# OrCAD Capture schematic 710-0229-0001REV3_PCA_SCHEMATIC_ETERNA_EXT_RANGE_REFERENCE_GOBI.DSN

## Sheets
1 01) Title: title: PCA SCH, ETERNA EXT RANGE REFERENCE, GOBI; rev: 03; note: 710-0229-0001
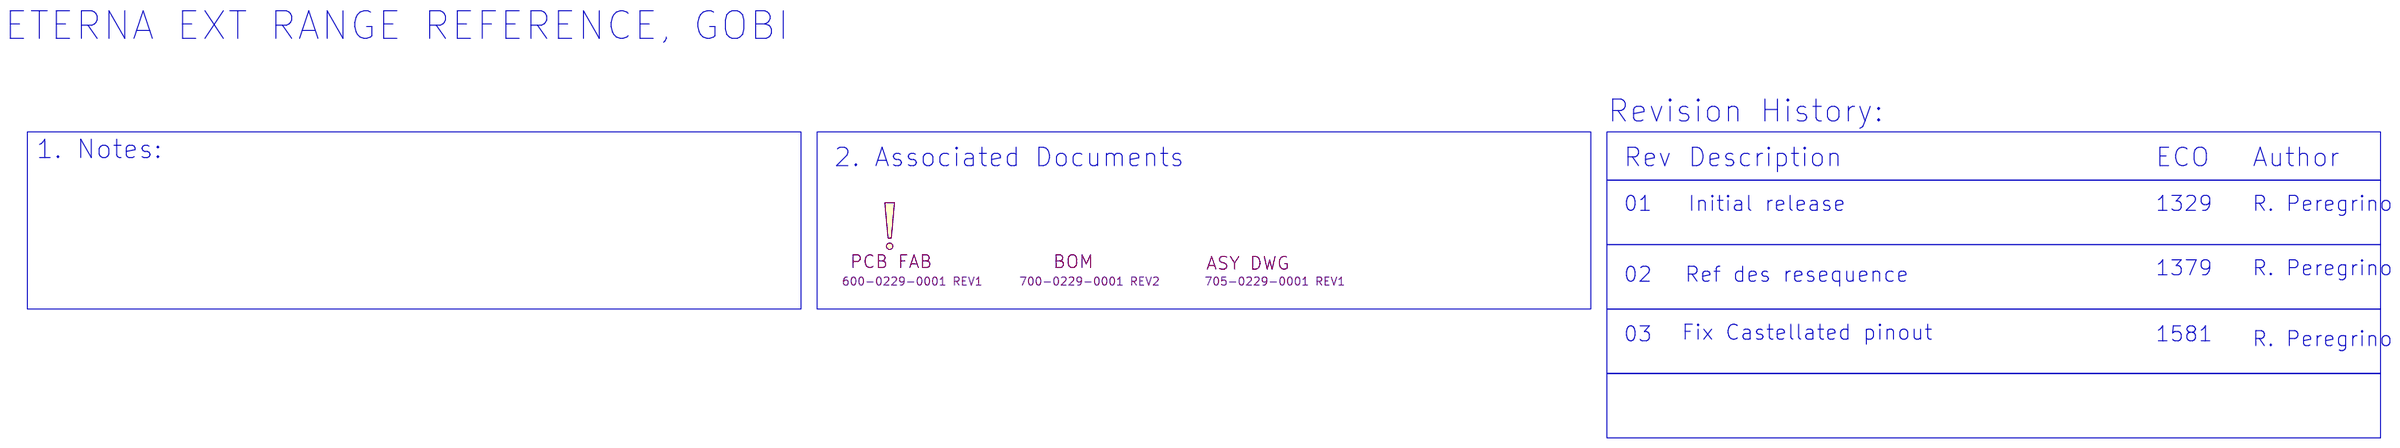
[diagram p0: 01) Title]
2 02) ETERNA: size B
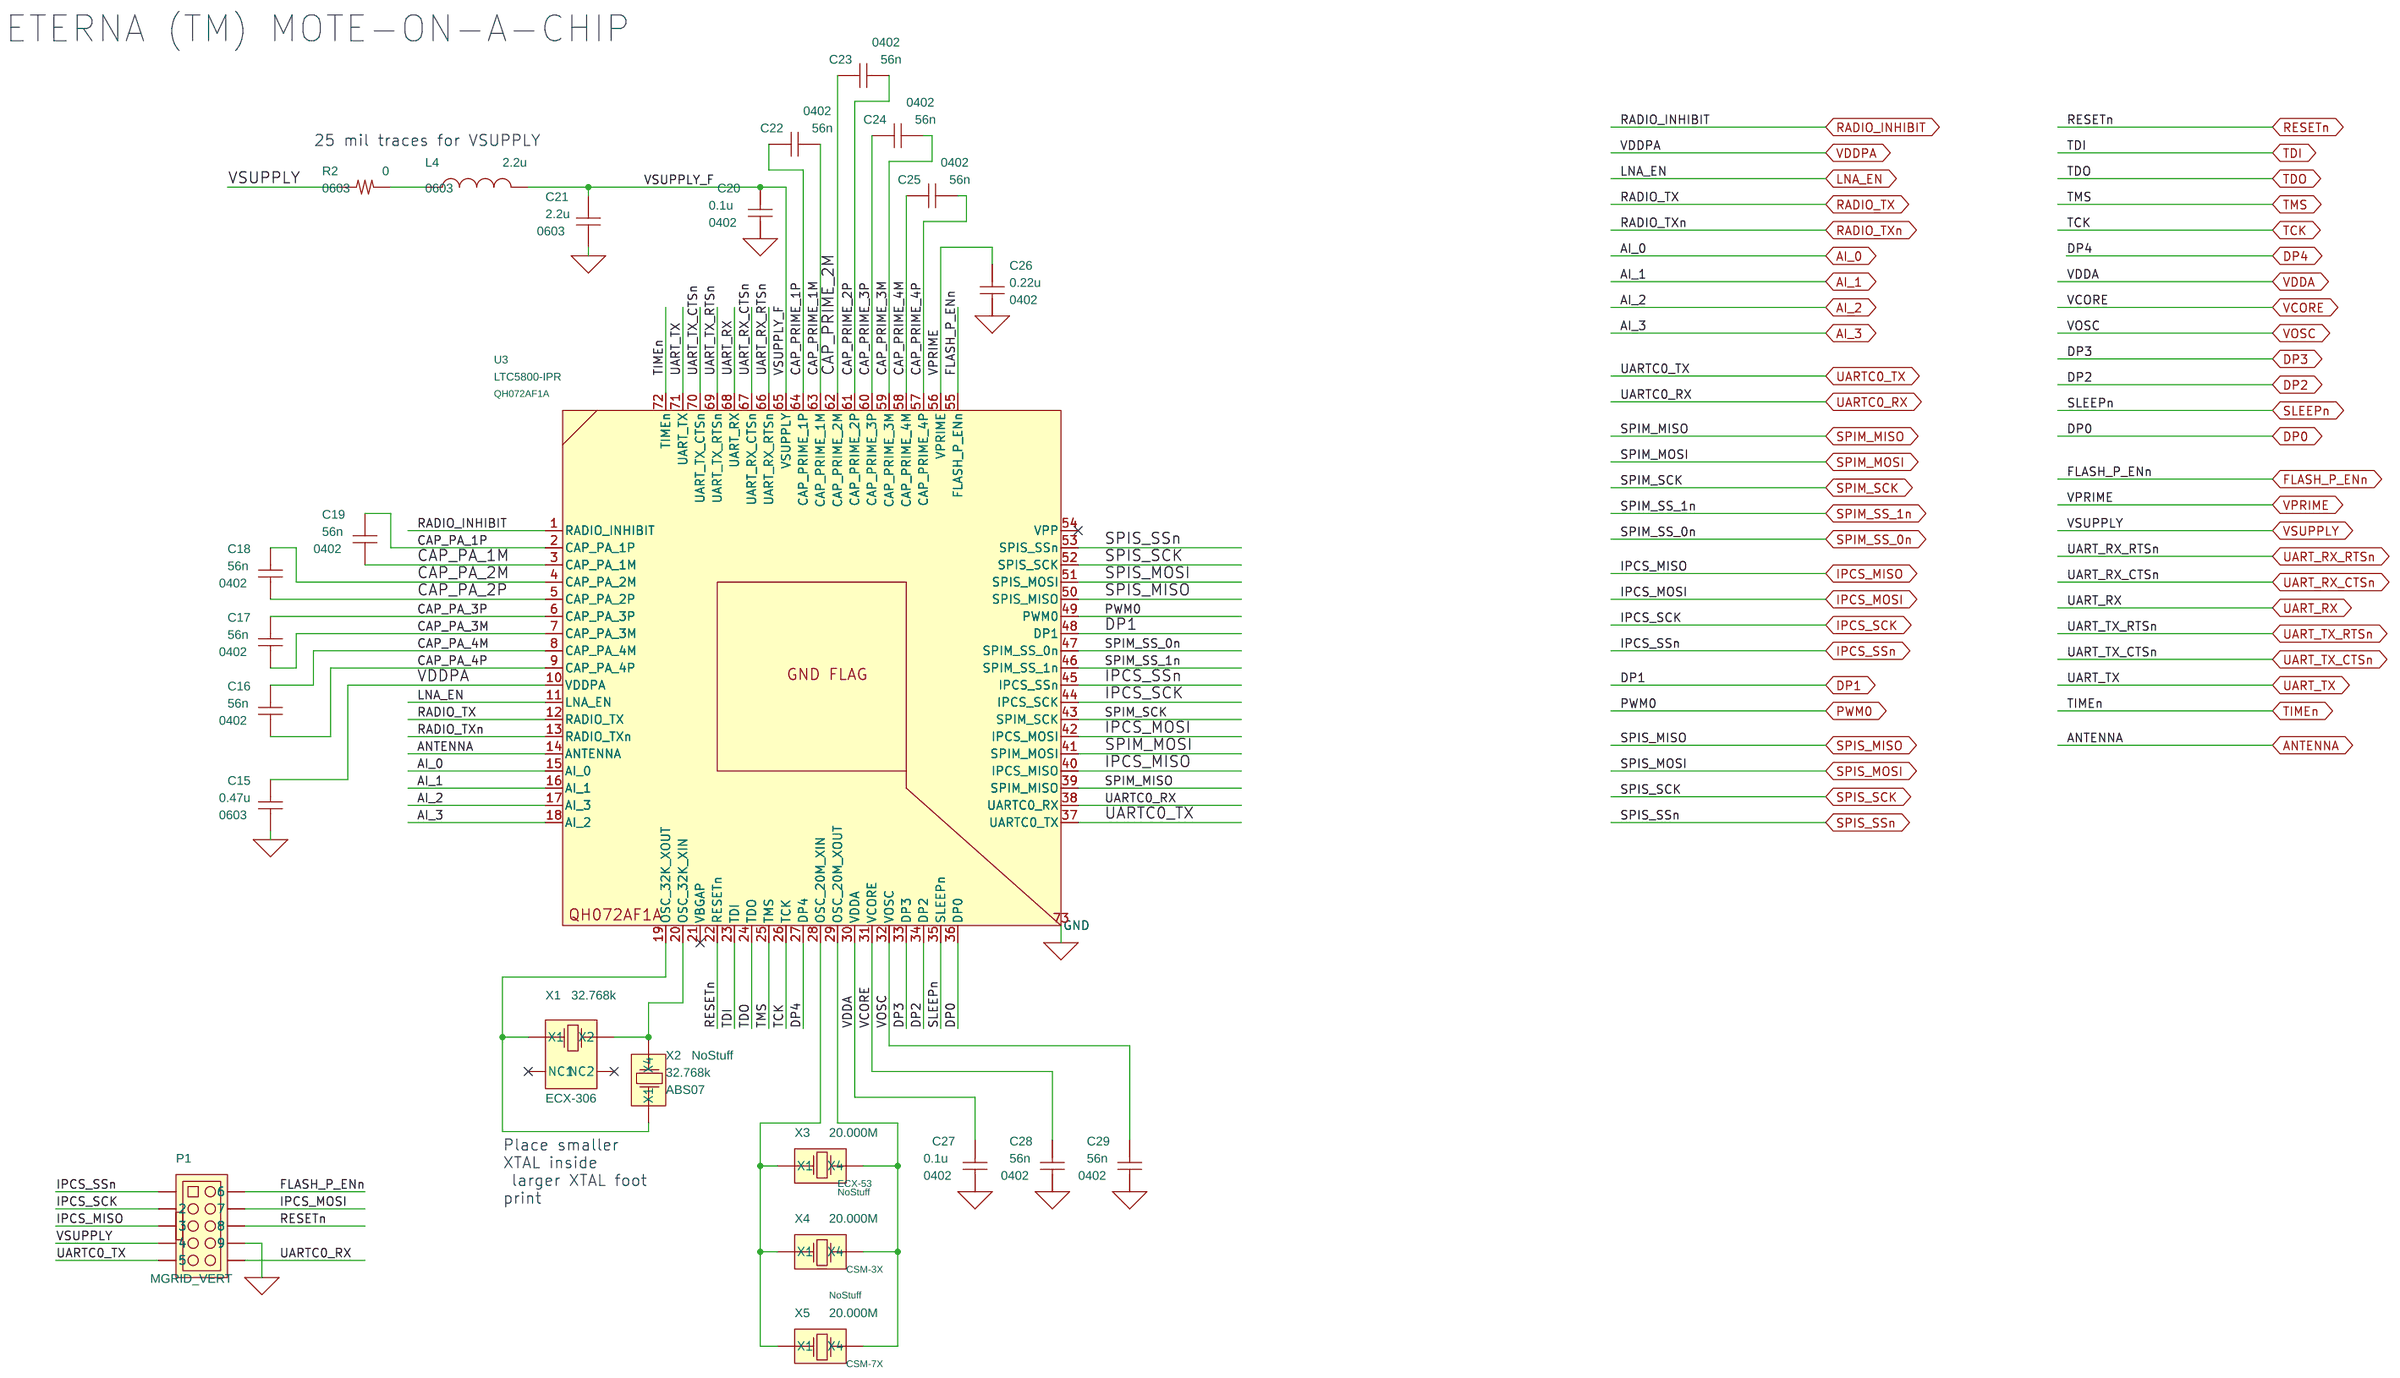
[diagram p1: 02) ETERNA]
3 03) CASTLE: size Custom
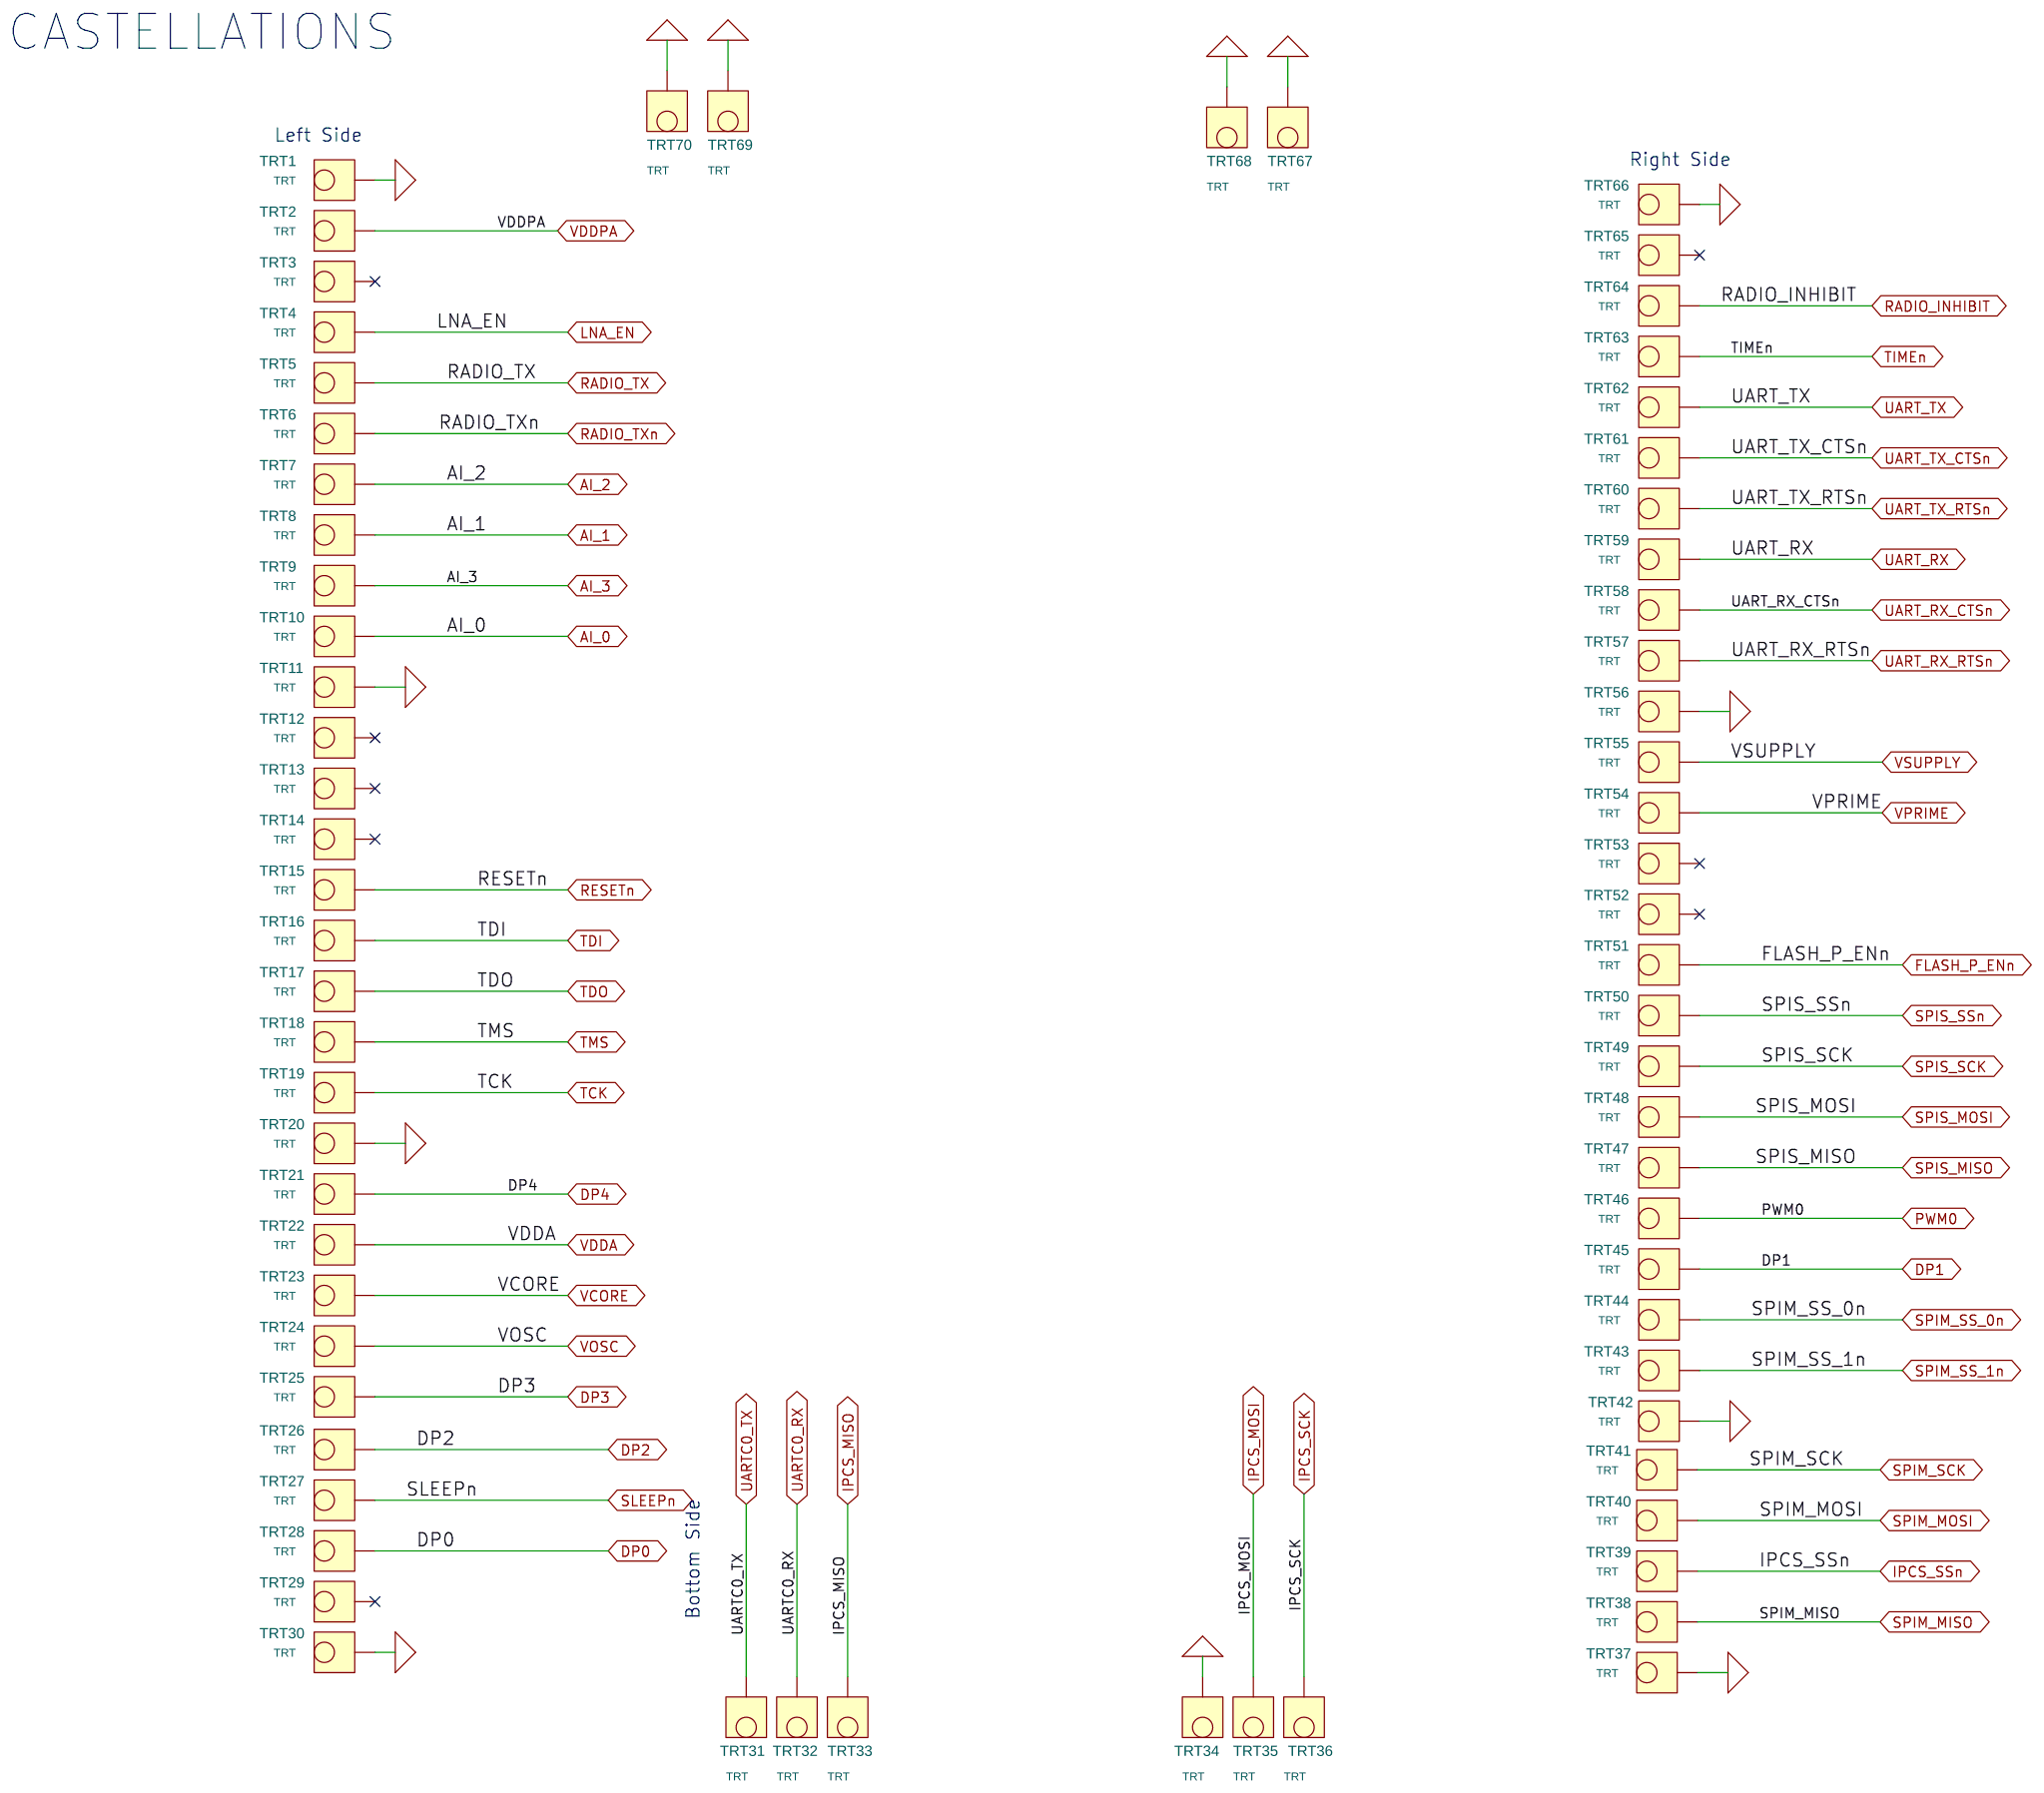
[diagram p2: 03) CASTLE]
4 04) PA, LNA: size B
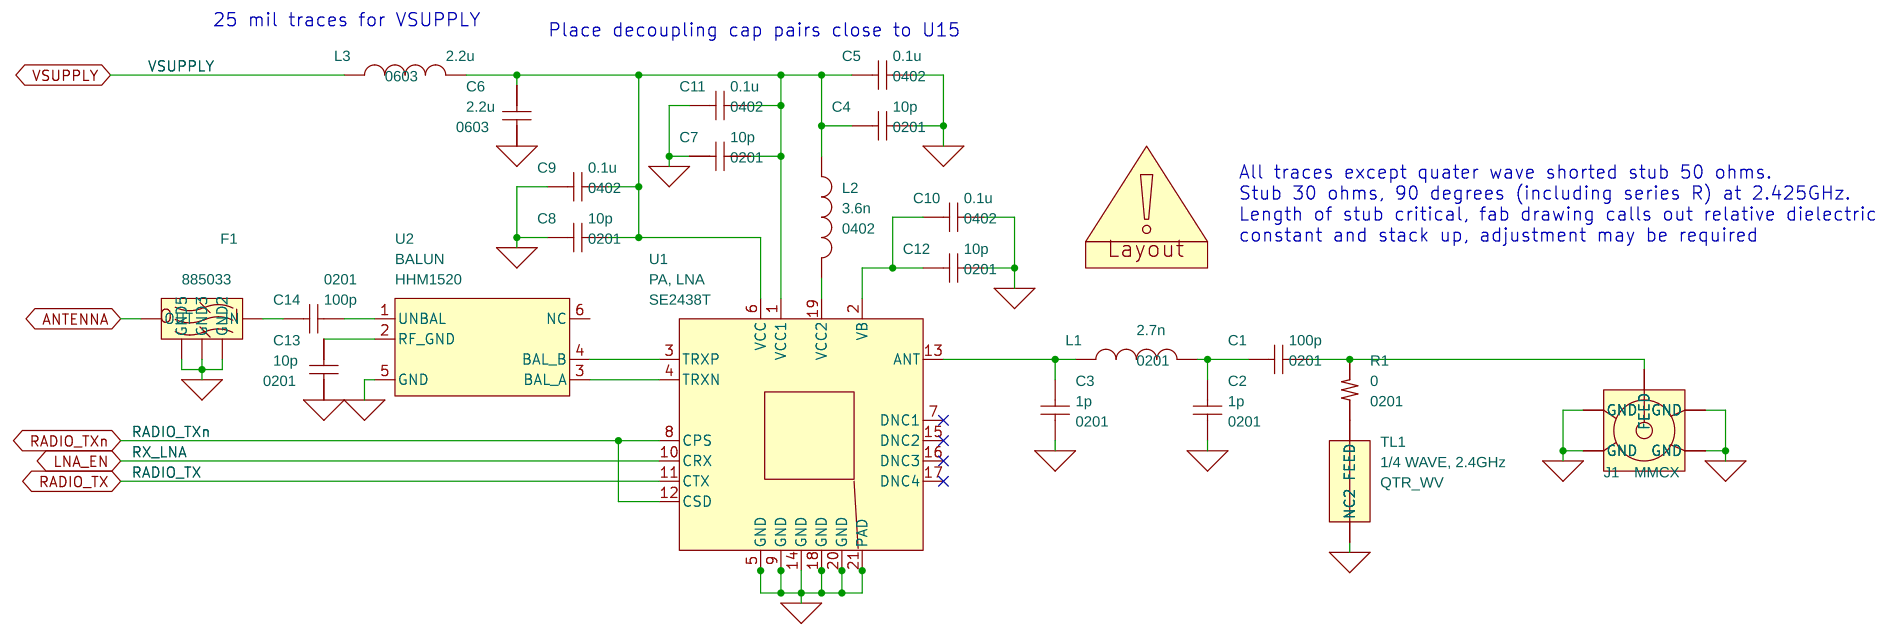
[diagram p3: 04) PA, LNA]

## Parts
sheet 01) Title
WARNINGL1  CALLOUT_PCB_FAB
WARNINGL2  CALLOUT_BOM
WARNINGL3  CALLOUT_ASSY_DWG
sheet 02) ETERNA
C15  0.47u  [0603]
C16  56n  [0402]
C17  56n  [0402]
C18  56n  [0402]
C19  56n  [0402]
C20  0.1u  [0402]
C21  2.2u  [0603]
C22  56n  [0402]
C23  56n  [0402]
C24  56n  [0402]
C25  56n  [0402]
C26  0.22u  [0402]
C27  0.1u  [0402]
C28  56n  [0402]
C29  56n  [0402]
L4  2.2u  [0603]
P1  MGRID_VERT  [HDR_2X5_2MM_SHRD]
R2  0  [0603]
U3  LTC5800-IPR  [QH072AF1A]
X1  32.768k  [ECX-306]
X2  32.768k  [ABS07]
X3  20.000M  [ECX-53]
X4  20.000M  [CSM-3X]
X5  20.000M  [CSM-7X]
sheet 03) CASTLE
TRT1  TP35_0  [TRT]
TRT2  TP35_0  [TRT]
TRT3  TP35_0  [TRT]
TRT4  TP35_0  [TRT]
TRT5  TP35_0  [TRT]
TRT6  TP35_0  [TRT]
TRT7  TP35_0  [TRT]
TRT8  TP35_0  [TRT]
TRT9  TP35_0  [TRT]
TRT10  TP35_0  [TRT]
TRT11  TP35_0  [TRT]
TRT12  TP35_0  [TRT]
TRT13  TP35_0  [TRT]
TRT14  TP35_0  [TRT]
TRT15  TP35_0  [TRT]
TRT16  TP35_0  [TRT]
TRT17  TP35_0  [TRT]
TRT18  TP35_0  [TRT]
TRT19  TP35_0  [TRT]
TRT20  TP35_0  [TRT]
TRT21  TP35_0  [TRT]
TRT22  TP35_0  [TRT]
TRT23  TP35_0  [TRT]
TRT24  TP35_0  [TRT]
TRT25  TP35_0  [TRT]
TRT26  TP35_0  [TRT]
TRT27  TP35_0  [TRT]
TRT28  TP35_0  [TRT]
TRT29  TP35_0  [TRT]
TRT30  TP35_0  [TRT]
TRT31  TP35_0  [TRT]
TRT32  TP35_0  [TRT]
TRT33  TP35_0  [TRT]
TRT34  TP35_0  [TRT]
TRT35  TP35_0  [TRT]
TRT36  TP35_0  [TRT]
TRT37  TP35_0  [TRT]
TRT38  TP35_0  [TRT]
TRT39  TP35_0  [TRT]
TRT40  TP35_0  [TRT]
TRT41  TP35_0  [TRT]
TRT42  TP35_0  [TRT]
TRT43  TP35_0  [TRT]
TRT44  TP35_0  [TRT]
TRT45  TP35_0  [TRT]
TRT46  TP35_0  [TRT]
TRT47  TP35_0  [TRT]
TRT48  TP35_0  [TRT]
TRT49  TP35_0  [TRT]
TRT50  TP35_0  [TRT]
TRT51  TP35_0  [TRT]
TRT52  TP35_0  [TRT]
TRT53  TP35_0  [TRT]
TRT54  TP35_0  [TRT]
TRT55  TP35_0  [TRT]
TRT56  TP35_0  [TRT]
TRT57  TP35_0  [TRT]
TRT58  TP35_0  [TRT]
TRT59  TP35_0  [TRT]
TRT60  TP35_0  [TRT]
TRT61  TP35_0  [TRT]
TRT62  TP35_0  [TRT]
TRT63  TP35_0  [TRT]
TRT64  TP35_0  [TRT]
TRT65  TP35_0  [TRT]
TRT66  TP35_0  [TRT]
TRT67  TP35_0  [TRT]
TRT68  TP35_0  [TRT]
TRT69  TP35_0  [TRT]
TRT70  TP35_0  [TRT]
sheet 04) PA, LNA
C1  100p  [0201]
C2  1p  [0201]
C3  1p  [0201]
C4  10p  [0201]
C5  0.1u  [0402]
C6  2.2u  [0603]
C7  10p  [0201]
C8  10p  [0201]
C9  0.1u  [0402]
C10  0.1u  [0402]
C11  0.1u  [0402]
C12  10p  [0201]
C13  10p  [0201]
C14  100p  [0201]
F1  885033  [CSP-5CT]
J1  .068" TAILS  [MMCX]
L1  2.7n  [0201]
L2  3.6n  [0402]
L3  2.2u  [0603]
R1  0  [0201]
TL1  1/4 WAVE, 2.4GHz  [QTR_WV]
U1  PA, LNA  [SE2438T]
U2  BALUN  [HHM1520]
WARNINGL4  NOTE_LAYOUT

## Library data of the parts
WARNINGL1 = CALLOUT_PCB_FAB: Part Number: 600-0229-0001 REV1
WARNINGL2 = CALLOUT_BOM: Part Number: 700-0229-0001 REV2
WARNINGL3 = CALLOUT_ASSY_DWG: Part Number: 705-0229-0001 REV1
C15 = CAP_0.47UF_10V_X7R_0603
C16-C19 C22-C25 C28 C29 = CAP_56nF_10V_X7R_0402
C5 C9-C11 C20 C27 = CAP_0.1UF_16V_X7R_0402
C6 C21 = CAP_2.2UF_6V3_X7R_0603
C26 = CAP_0.22UF_6V3_X7R_0402
L3 L4 = IND_2.2uH_120mA_20%_0603
P1 = HDR_5x2_2MM_PTH_SHRD
R2 = RES_0.0_1A_JMPR_0603: RES, 0, JUMPER, 0603, SMD
U3 = LTC5800IWR-IPMA: Part Number: 280-0362; Stuff: ALT_PN=280-0357
X1 = XTAL_32kHZ_ECX-306
X2 = XTAL_32kHz_ABS07: Stuff: NoStuff
X3 = XTAL_20MHz_ECX-53: Stuff: NoStuff
X4 = XTAL_20.000MHZ_CRTL_ECS-CSM3X
X5 = XTAL_20.000MHZ_CTRL_ECS-CSM7X: Stuff: NoStuff
TRT1-TRT70 = TRT: Dist PN: NA; Manuf PN: NA
C1 C14 = CAP_100PF_25V_COG_0201
C2 C3 = CAP_1PF_25V_COG_0201
C4 C7 C8 C12 C13 = CAP_10PF_25V_COG_0201
F1 = BAW_2G4_885033
J1 = COAX_MMCX_PTH_SHORT_PINS
L1 = IND_2.7nH_FIXME_0201
L2 = IND_3.6nH_FIXME_0402
R1 = RES_0.0_0A5_JMPR_0201: RES, 0, JUMPER, 0201, SMD
TL1 = STUB_1_4_WAVE_2.4GHZ: PCB FEATURE, 1/4 WAVE STUB @ 2.4GHz
U1 = IC_SE2438T: IC TRANSP LATCH OCT D DHVQFN20_NXP_74AHC573BQ,115; Part Number: 280-0350
U2 = XFMR_HHM1520: IC TRANSP LATCH OCT D DHVQFN20_NXP_74AHC573BQ,115; Part Number: 201-0004
WARNINGL4 = NOTE_LAYOUT

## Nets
GND_SIGNAL: C2.2 C3.2 C4.1 C5.1 C6.2 C7.1 C8.1 C9.1 C10.1 C11.1 C12.1 C13.2 C15.2 C20.2 C21.2 C26.2 C27.2 C28.2 C29.2 F1.2(GND2) F1.3(GND3) F1.5(GND5) J1.2(GND) J1.3(GND) J1.4(GND) J1.5(GND) P1.8(9) TL1.2(NC2) TRT1.1(TP) TRT11.1(TP) TRT20.1(TP) TRT30.1(TP) TRT34.1(TP) TRT37.1(TP) TRT42.1(TP) TRT56.1(TP) TRT66.1(TP) TRT67.1(TP) TRT68.1(TP) TRT69.1(TP) TRT70.1(TP) U1.5(GND) U1.9(GND) U1.14(GND) U1.18(GND) U1.20(GND) U1.21(PAD) U2.5(GND) U3.73(GND)
VDDA: C27.1 TRT22.1(TP) U3.30(VDDA)
VDDPA: C15.1 TRT2.1(TP) U3.10(VDDPA)
AI_0: TRT10.1(TP) U3.15(AI_0)
AI_1: TRT8.1(TP) U3.16(AI_1)
AI_2: TRT7.1(TP) U3.17(AI_3)
AI_3: TRT9.1(TP) U3.18(AI_2)
ANTENNA: F1.4(OUT) U3.14(ANTENNA)
CAP_PA_1M: C19.2 U3.3(CAP_PA_1M)
CAP_PA_1P: C19.1 U3.2(CAP_PA_1P)
CAP_PA_2M: C18.1 U3.4(CAP_PA_2M)
CAP_PA_2P: C18.2 U3.5(CAP_PA_2P)
CAP_PA_3M: C17.2 U3.7(CAP_PA_3M)
CAP_PA_3P: C17.1 U3.6(CAP_PA_3P)
CAP_PA_4M: C16.1 U3.8(CAP_PA_4M)
CAP_PA_4P: C16.2 U3.9(CAP_PA_4P)
CAP_PRIME_1M: C22.2 U3.63(CAP_PRIME_1M)
CAP_PRIME_1P: C22.1 U3.64(CAP_PRIME_1P)
CAP_PRIME_2M: C23.1 U3.62(CAP_PRIME_2M)
CAP_PRIME_2P: C23.2 U3.61(CAP_PRIME_2P)
CAP_PRIME_3M: C24.2 U3.59(CAP_PRIME_3M)
CAP_PRIME_3P: C24.1 U3.60(CAP_PRIME_3P)
CAP_PRIME_4M: C25.1 U3.58(CAP_PRIME_4M)
CAP_PRIME_4P: C25.2 U3.57(CAP_PRIME_4P)
DP0: TRT28.1(TP) U3.36(DP0)
DP1: TRT45.1(TP) U3.48(DP1)
DP2: TRT26.1(TP) U3.34(DP2)
DP3: TRT25.1(TP) U3.33(DP3)
DP4: TRT21.1(TP) U3.27(DP4)
FLASH_P_ENn: P1.2(6) TRT51.1(TP) U3.55(FLASH_P_ENn)
IPCS_MISO: P1.5(3) TRT33.1(TP) U3.40(IPCS_MISO)
IPCS_MOSI: P1.4(7) TRT35.1(TP) U3.42(IPCS_MOSI)
IPCS_SCK: P1.3(2) TRT36.1(TP) U3.44(IPCS_SCK)
IPCS_SSn: P1.1 TRT39.1(TP) U3.45(IPCS_SSn)
LNA_EN: TRT4.1(TP) U1.10(CRX) U3.11(LNA_EN)
PWM0: TRT46.1(TP) U3.49(PWM0)
RADIO_INHIBIT: TRT64.1(TP) U3.1(RADIO_INHIBIT)
RADIO_TX: TRT5.1(TP) U1.11(CTX) U3.12(RADIO_TX)
RADIO_TXn: TRT6.1(TP) U1.8(CPS) U1.12(CSD) U3.13(RADIO_TXn)
RESETn: P1.6(8) TRT15.1(TP) U3.22(RESETn)
SLEEPn: TRT27.1(TP) U3.35(SLEEPn)
SPIM_MISO: TRT38.1(TP) U3.39(SPIM_MISO)
SPIM_MOSI: TRT40.1(TP) U3.41(SPIM_MOSI)
SPIM_SCK: TRT41.1(TP) U3.43(SPIM_SCK)
SPIM_SS_0n: TRT44.1(TP) U3.47(SPIM_SS_0n)
SPIM_SS_1n: TRT43.1(TP) U3.46(SPIM_SS_1n)
SPIS_MISO: TRT47.1(TP) U3.50(SPIS_MISO)
SPIS_MOSI: TRT48.1(TP) U3.51(SPIS_MOSI)
SPIS_SCK: TRT49.1(TP) U3.52(SPIS_SCK)
SPIS_SSn: TRT50.1(TP) U3.53(SPIS_SSn)
TCK: TRT19.1(TP) U3.26(TCK)
TDI: TRT16.1(TP) U3.23(TDI)
TDO: TRT17.1(TP) U3.24(TDO)
TIMEn: TRT63.1(TP) U3.72(TIMEn)
TMS: TRT18.1(TP) U3.25(TMS)
UART_RX: TRT59.1(TP) U3.68(UART_RX)
UART_RX_CTSn: TRT58.1(TP) U3.67(UART_RX_CTSn)
UART_RX_RTSn: TRT57.1(TP) U3.66(UART_RX_RTSn)
UART_TX: TRT62.1(TP) U3.71(UART_TX)
UART_TX_CTSn: TRT61.1(TP) U3.70(UART_TX_CTSn)
UART_TX_RTSn: TRT60.1(TP) U3.69(UART_TX_RTSn)
UARTC0_RX: P1.10 TRT32.1(TP) U3.38(UARTC0_RX)
UARTC0_TX: P1.9(5) TRT31.1(TP) U3.37(UARTC0_TX)
VCORE: C28.1 TRT23.1(TP) U3.31(VCORE)
VOSC: C29.1 TRT24.1(TP) U3.32(VOSC)
VPRIME: C26.1 TRT54.1(TP) U3.56(VPRIME)
VSUPPLY: L3.1 P1.7(4) R2.1 TRT55.1(TP)
VSUPPLY_F: C20.1 C21.1 L4.2 U3.65(VSUPPLY)
N20011889: U3.29(OSC_20M_XOUT) X3.2(X4) X4.2(X4) X5.2(X4)
N20012188: L4.1 R2.2
N20012463: U3.19(OSC_32K_XOUT) X1.1(X1) X2.1(X1)
N20012489: U3.20(OSC_32K_XIN) X1.4(X2) X2.2(X4)
N20013302: U3.28(OSC_20M_XIN) X3.1(X1) X4.1(X1) X5.1(X1)
N20148236: U1.4(TRXN) U2.3(BAL_A)
N20148238: U1.3(TRXP) U2.4(BAL_B)
N20148251: C13.1 U2.2(RF_GND)
N20148337: C3.1 L1.1 U1.13(ANT)
N20149811: C1.1 C2.1 L1.2
N20154567: C4.2 C5.2 C6.1 C7.2 C8.2 C9.2 C11.2 L2.2 L3.2 U1.1(VCC1) U1.6(VCC)
N20163557: L2.1 U1.19(VCC2)
N20165496: C10.2 C12.2 U1.2(VB)
N20180437: C14.2 U2.1(UNBAL)
N20625377: C1.2 J1.1(FEED) R1.2
N20653835: C14.1 F1.1(IN)
N20706107: R1.1 TL1.1(FEED)

Not connected (* = marked no-connect by the designer): TRT3 1(TP)*; TRT12 1(TP)*; TRT13 1(TP)*; TRT14 1(TP)*; TRT29 1(TP)*; TRT52 1(TP)*; TRT53 1(TP)*; TRT65 1(TP)*; U1 7(DNC1)* 15(DNC2)* 16(DNC3)* 17(DNC4)*; U2 6(NC); U3 21(VBGAP)* 54(VPP)*; X1 2(NC1)* 3(NC2)*

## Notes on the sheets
sheet 1
- ETERNA EXT RANGE REFERENCE, GOBI
- Revision History:
- 1. Notes:
- 2. Associated Documents
- Rev
- Description
- ECO
- Author
- 01
- Initial release
- 1329
- R. Peregrino
- 02
- Ref des resequence
- 1379
- R. Peregrino
- 03
- Fix Castellated pinout
- 1581
- R. Peregrino
sheet 2
- ETERNA (TM) MOTE-ON-A-CHIP
- 25 mil traces for VSUPPLY
- Place smaller
  XTAL inside
   larger XTAL foot
  print
sheet 3
- CASTELLATIONS
- Left Side
- Right Side
- Bottom Side
sheet 4
- 25 mil traces for VSUPPLY
- Place decoupling cap pairs close to U15
- All traces except quater wave shorted stub 50 ohms.
  Stub 30 ohms, 90 degrees (including series R) at 2.425GHz.
  Length of stub critical, fab drawing calls out relative dielectric
  constant and stack up, adjustment may be required
